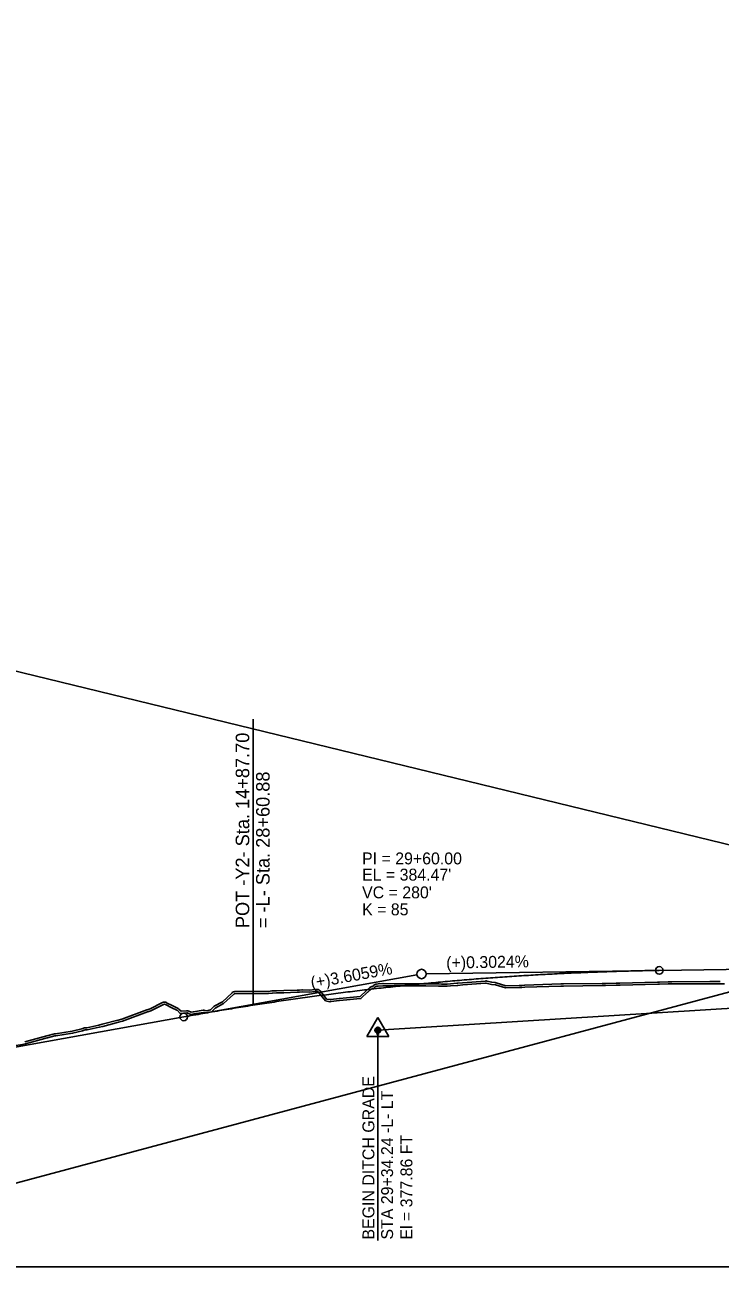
# Model space of a CAD drawing. Extents: x 1625686 to 1640492, y 1161393 to 1175642.
# Drawn here: x 1637638 to 1638048, y 1174911 to 1175642 of the extents above; entities that cross this region are included whole.
import ezdxf

# ---------------------------------------------------------------- set-up
doc = ezdxf.new("R2010")
doc.units = 0
for name, color, linetype in [('Exist Profile Cell', 7, 'Continuous'), ('Prop PFL Text', 7, 'Continuous'), ('Prop Vertical Profile Curve Label', 7, 'Continuous'), ('Prop Vertical Profile Ditch Grade Left', 7, 'Continuous'), ('Prop Vertical Profile Grade', 7, 'Continuous'), ('Prop Vertical Profile Grade Label', 7, 'Continuous'), ('Prop VPI Ditch Grade Left Label', 7, 'Continuous'), ('Prop VPI Label', 7, 'Continuous'), ('Scratch_Level_1', 7, 'Continuous'), ('Scratch_Level_3', 7, 'Continuous')]:
    doc.layers.add(name, color=color, linetype=linetype)

msp = doc.modelspace()

# ---------------------------------------------------------------- linework, layer by layer
at = {"layer": 'Exist Profile Cell'}
msp.add_line((1635911.78, 1174910.79), (1640378.1, 1174910.79), dxfattribs=at)
at = {"layer": 'Prop PFL Text'}
msp.add_line((1637772.66, 1175064.77), (1637772.66, 1175233.25), dxfattribs=at)
at = {"layer": 'Prop Vertical Profile Curve Label'}
for centre in [(1638011.78, 1175085.25), (1637731.78, 1175057.9)]:
    msp.add_circle(centre, 2.25, dxfattribs=at)
at = {"layer": 'Prop Vertical Profile Ditch Grade Left'}
msp.add_line((1637846.02, 1175050.09), (1638361.78, 1175082.04), dxfattribs=at)
at = {"layer": 'Prop Vertical Profile Grade'}
for p, q in [((1638011.78, 1175085.25), (1638636.78, 1175094.7)), ((1637591.78, 1175032.65), (1637731.78, 1175057.9))]:
    msp.add_line(p, q, dxfattribs=at)
msp.add_spline([(1637731.78, 1175057.9), (1637737.38, 1175058.9), (1637742.98, 1175059.88), (1637748.58, 1175060.84), (1637754.18, 1175061.79), (1637759.78, 1175062.71), (1637765.38, 1175063.62), (1637770.98, 1175064.51), (1637776.58, 1175065.38), (1637782.18, 1175066.23), (1637787.78, 1175067.07), (1637793.38, 1175067.88), (1637798.98, 1175068.68), (1637804.58, 1175069.46), (1637810.18, 1175070.22), (1637815.78, 1175070.96), (1637821.38, 1175071.68), (1637826.98, 1175072.39), (1637832.58, 1175073.07), (1637838.18, 1175073.74), (1637843.78, 1175074.39), (1637849.38, 1175075.02), (1637854.98, 1175075.63), (1637860.58, 1175076.22), (1637866.18, 1175076.8), (1637871.78, 1175077.36), (1637877.38, 1175077.89), (1637882.98, 1175078.41), (1637888.58, 1175078.91), (1637894.18, 1175079.4), (1637899.78, 1175079.86), (1637905.38, 1175080.31), (1637910.98, 1175080.73), (1637916.58, 1175081.14), (1637922.18, 1175081.53), (1637927.78, 1175081.9), (1637933.38, 1175082.26), (1637938.98, 1175082.59), (1637944.58, 1175082.91), (1637950.18, 1175083.2), (1637955.78, 1175083.48), (1637961.38, 1175083.74), (1637966.98, 1175083.98), (1637972.58, 1175084.21), (1637978.18, 1175084.41), (1637983.78, 1175084.6), (1637989.38, 1175084.77), (1637994.98, 1175084.92), (1638000.58, 1175085.05), (1638006.18, 1175085.16), (1638011.78, 1175085.25)], degree=3, dxfattribs=at)
at = {"layer": 'Prop VPI Ditch Grade Left Label'}
for p, q in [((1637846.02, 1175057.57), (1637839.57, 1175046.37)), ((1637846.02, 1175057.57), (1637852.52, 1175046.37)), ((1637846.02, 1175050.09), (1637846.02, 1174926.27)), ((1637839.57, 1175046.37), (1637852.52, 1175046.37))]:
    msp.add_line(p, q, dxfattribs=at)
for centre, radius in [((1637846.02, 1175050.09), 1.75), ((1637846.02, 1175050.09), 1.2), ((1637846.02, 1175050.09), 0.5), ((1637846.02, 1175047.79), 0.5)]:
    msp.add_circle(centre, radius, dxfattribs=at)
at = {"layer": 'Prop VPI Label'}
for p, q in [((1637731.78, 1175057.9), (1637869.08, 1175082.65)), ((1638011.78, 1175085.25), (1637874.53, 1175083.18))]:
    msp.add_line(p, q, dxfattribs=at)
msp.add_circle((1637871.78, 1175083.14), 2.75, dxfattribs=at)
at = {"layer": 'Scratch_Level_1'}
for p, q in [((1637783.91, 1175073.18), (1637786.36, 1175073.27)), ((1637783.95, 1175071.93), (1637786.4, 1175072.02)), ((1637811.05, 1175072.42), (1637813.26, 1175069.71)), ((1637812.02, 1175073.2), (1637814.23, 1175070.5)), ((1637839.3, 1175073.42), (1637841.41, 1175075.21)), ((1637840.11, 1175072.47), (1637842.22, 1175074.25)), ((1637843.02, 1175075.8), (1637843.69, 1175076.47)), ((1637895.97, 1175077.97), (1637909.45, 1175079.02)), ((1637896.07, 1175076.72), (1637909.55, 1175077.77)), ((1637932.63, 1175076.59), (1637953.79, 1175077.3)), ((1637932.67, 1175075.34), (1637953.84, 1175076.05)), ((1638019.27, 1175078.58), (1638041.48, 1175078.69)), ((1638019.27, 1175077.33), (1638041.49, 1175077.44)), ((1637737.46, 1175060.89), (1637743.18, 1175061.77)), ((1637737.65, 1175059.65), (1637743.37, 1175060.53)), ((1637638.17, 1175043.3), (1637651.09, 1175046.76)), ((1637638.49, 1175042.09), (1637651.41, 1175045.55)), ((1637651.14, 1175046.77), (1637655.61, 1175047.87)), ((1637651.44, 1175045.56), (1637655.91, 1175046.66)), ((1637655.72, 1175047.89), (1637656.05, 1175047.96)), ((1637655.96, 1175046.67), (1637656.3, 1175046.74))]:
    msp.add_line(p, q, dxfattribs=at)
for points in [[(1637749.73, 1175064.15), (1637754.49, 1175066.71), (1637760.18, 1175072.08)], [(1637761.88, 1175072.76), (1637781.57, 1175072.92), (1637783.71, 1175073.17)], [(1637786.37, 1175073.27), (1637790.73, 1175073.4), (1637798.48, 1175073.62), (1637799.91, 1175073.71), (1637801.34, 1175073.81)], [(1637786.41, 1175072.02), (1637790.76, 1175072.15), (1637798.54, 1175072.37), (1637799.99, 1175072.47), (1637801.42, 1175072.56)], [(1637801.54, 1175072.56), (1637805.76, 1175072.4), (1637809.2, 1175072.78), (1637809.94, 1175072.87)], [(1637801.59, 1175073.81), (1637805.72, 1175073.65), (1637809.06, 1175074.03), (1637809.8, 1175074.11)], [(1637833.66, 1175069.7), (1637835.56, 1175069.86), (1637839.19, 1175073.32)], [(1637833.76, 1175068.46), (1637836.1, 1175068.65), (1637836.29, 1175068.82), (1637840.05, 1175072.42)], [(1637843.21, 1175074.54), (1637843.49, 1175074.5), (1637844.57, 1175075.59)], [(1637845.29, 1175077.21), (1637846.25, 1175077.27), (1637849, 1175077.46)], [(1637845.38, 1175075.96), (1637846.34, 1175076.03), (1637849.09, 1175076.21)], [(1637849.18, 1175076.22), (1637855.7, 1175076.18), (1637864.97, 1175076.14), (1637870.88, 1175076.11), (1637872.93, 1175076.14)], [(1637849.19, 1175077.47), (1637855.7, 1175077.43), (1637864.97, 1175077.39), (1637870.88, 1175077.36), (1637872.9, 1175077.39)], [(1637872.96, 1175076.14), (1637874.24, 1175076.13), (1637881.77, 1175076.06)], [(1637872.97, 1175077.39), (1637874.26, 1175077.38), (1637881.78, 1175077.31)], [(1637881.82, 1175076.06), (1637883.53, 1175075.97), (1637886.92, 1175075.97), (1637888.87, 1175076.11), (1637892.68, 1175076.4), (1637893.25, 1175076.44), (1637896.04, 1175076.72)], [(1637881.88, 1175077.31), (1637883.56, 1175077.22), (1637886.87, 1175077.22), (1637888.78, 1175077.36), (1637892.58, 1175077.65), (1637893.14, 1175077.69), (1637895.92, 1175077.97)], [(1637909.94, 1175077.74), (1637912.9, 1175077.02), (1637915.12, 1175076.81)], [(1637910.24, 1175078.96), (1637913.11, 1175078.26), (1637915.23, 1175078.05)], [(1637915.36, 1175076.76), (1637921.32, 1175074.96), (1637929.4, 1175075.14), (1637930.95, 1175075.18), (1637932.6, 1175075.34)], [(1637915.72, 1175077.96), (1637921.49, 1175076.21), (1637929.37, 1175076.39), (1637930.88, 1175076.43), (1637932.48, 1175076.58)], [(1637953.9, 1175076.05), (1637954.65, 1175076.03), (1637955.45, 1175076.04), (1637978.16, 1175076.36)], [(1637953.93, 1175077.3), (1637954.66, 1175077.28), (1637955.44, 1175077.29), (1637978.14, 1175077.61)], [(1637978.2, 1175076.36), (1637979.1, 1175076.35), (1637980.08, 1175076.38)], [(1637978.23, 1175077.61), (1637979.09, 1175077.6), (1637980.03, 1175077.63)], [(1637980.09, 1175077.63), (1637986.33, 1175077.72), (1637987.41, 1175077.76)], [(1637980.11, 1175076.38), (1637986.36, 1175076.47), (1637987.45, 1175076.51)], [(1637987.51, 1175076.51), (1637988.68, 1175076.49), (1638010.87, 1175077.16)], [(1637987.54, 1175077.76), (1637988.67, 1175077.74), (1638010.84, 1175078.41)], [(1638010.9, 1175078.41), (1638011.87, 1175078.42), (1638017.05, 1175078.57)], [(1638010.91, 1175077.16), (1638011.89, 1175077.17), (1638017.09, 1175077.33)], [(1638017.19, 1175077.32), (1638018.16, 1175077.28), (1638019.22, 1175077.33)], [(1638017.26, 1175078.57), (1638018.16, 1175078.53), (1638019.16, 1175078.58)], [(1638041.53, 1175077.44), (1638042.66, 1175077.41), (1638047.5, 1175077.43)], [(1638041.56, 1175078.69), (1638042.67, 1175078.66), (1638047.5, 1175078.68)], [(1638047.58, 1175077.43), (1638048.8, 1175077.36), (1638050.17, 1175077.34)], [(1637710.23, 1175062.14), (1637711.93, 1175062.59), (1637719.22, 1175066.28)], [(1637710.55, 1175060.93), (1637712.38, 1175061.41), (1637719.78, 1175065.16)], [(1637720.93, 1175065.15), (1637724.69, 1175063.18), (1637727.62, 1175061.87)], [(1637721.51, 1175066.26), (1637725.24, 1175064.31), (1637728.14, 1175063.01)], [(1637750.32, 1175063.05), (1637755.23, 1175065.68), (1637761.04, 1175071.17)], [(1637761.89, 1175071.51), (1637781.65, 1175071.67), (1637783.85, 1175071.92)], [(1637813.26, 1175069.71), (1637815.24, 1175067.26), (1637817.83, 1175066.78), (1637818.46, 1175066.86), (1637823.5, 1175067.51)], [(1637814.23, 1175070.49), (1637815.92, 1175068.4), (1637817.87, 1175068.04), (1637818.3, 1175068.1), (1637823.34, 1175068.75)], [(1637823.44, 1175068.76), (1637827.65, 1175069.15), (1637833.63, 1175069.7)], [(1637823.55, 1175067.52), (1637827.77, 1175067.91), (1637833.74, 1175068.46)], [(1637693.08, 1175056.05), (1637695.35, 1175056.59), (1637709.98, 1175062.06)], [(1637693.37, 1175054.83), (1637695.72, 1175055.39), (1637710.42, 1175060.89)], [(1637727.99, 1175061.62), (1637729.74, 1175059.91), (1637733.55, 1175060.27)], [(1637728.86, 1175062.51), (1637730.2, 1175061.21), (1637733.43, 1175061.52)], [(1637734.23, 1175060.15), (1637735.92, 1175059.31), (1637737.6, 1175059.64)], [(1637734.78, 1175061.27), (1637736.1, 1175060.62), (1637737.35, 1175060.87)], [(1637743.82, 1175060.52), (1637745.32, 1175060.2), (1637748.19, 1175060.92), (1637750.02, 1175062.82)], [(1637744.08, 1175061.74), (1637745.3, 1175061.48), (1637747.54, 1175062.05), (1637749.11, 1175063.68)], [(1637656.16, 1175047.98), (1637666.06, 1175049.52), (1637671.72, 1175050.94), (1637673.35, 1175051.38)], [(1637656.35, 1175046.75), (1637666.3, 1175048.29), (1637672.04, 1175049.73), (1637673.68, 1175050.18)], [(1637674.06, 1175050.22), (1637674.39, 1175050.2), (1637674.78, 1175050.23), (1637681.99, 1175051.8), (1637684.01, 1175052.32), (1637693.34, 1175054.82)], [(1637674.12, 1175051.47), (1637674.38, 1175051.46), (1637674.61, 1175051.47), (1637681.71, 1175053.01), (1637683.69, 1175053.53), (1637693.01, 1175056.03)], [(1637615.09, 1175038.35), (1637636.81, 1175041.69), (1637637.61, 1175041.85), (1637638.48, 1175042.09)]]:
    msp.add_lwpolyline(points, dxfattribs=at)
for centre, radius, start, end in [((1637761.9, 1175070.26), 2.5, 90.45637, 133.36574), ((1637784, 1175070.68), 2.5, 92.0965, 96.67071), ((1637786.45, 1175070.77), 2.5, 91.66065, 92.0965), ((1637786.45, 1175070.77), 1.25, 91.66065, 92.0965), ((1637801.5, 1175071.31), 2.5, 87.79624, 93.66933), ((1637801.5, 1175071.31), 1.25, 87.79624, 93.66933), ((1637810.08, 1175071.63), 2.5, 39.17888, 96.41969), ((1637810.08, 1175071.63), 1.25, 39.17888, 96.41969), ((1637840.92, 1175071.52), 2.5, 130.21039, 133.69679), ((1637840.92, 1175071.52), 1.25, 130.21039, 133.69679), ((1637843.03, 1175073.3), 2.5, 90.24247, 130.21039), ((1637843.03, 1175073.3), 1.25, 81.82241, 130.21039), ((1637845.46, 1175074.71), 2.5, 93.90401, 135.22839), ((1637845.46, 1175074.71), 1.25, 93.90401, 135.22839), ((1637849.17, 1175074.97), 2.5, 89.70817, 93.90986), ((1637849.17, 1175074.97), 1.25, 89.70817, 93.90986), ((1637872.95, 1175074.89), 2.5, 89.42738, 90.97147), ((1637872.95, 1175074.89), 1.25, 89.42738, 90.97147), ((1637881.76, 1175074.81), 1.25, 87.22873, 89.44288), ((1637881.76, 1175074.81), 2.5, 87.22873, 89.44288), ((1637896.17, 1175075.48), 2.5, 94.45073, 95.67591), ((1637896.17, 1175075.48), 1.25, 94.45073, 95.67591), ((1637909.64, 1175076.53), 2.5, 76.3014, 94.45073), ((1637909.64, 1175076.53), 1.25, 76.3014, 94.45073), ((1637915, 1175075.56), 1.25, 73.17049, 84.52842), ((1637915, 1175075.56), 2.5, 73.17049, 84.52842), ((1637932.71, 1175074.09), 2.5, 91.91962, 95.25594), ((1637932.71, 1175074.09), 1.25, 91.91962, 95.25594), ((1637953.88, 1175074.8), 2.5, 88.74727, 91.91962), ((1637953.88, 1175074.8), 1.25, 88.74727, 91.91962), ((1637978.18, 1175075.11), 2.5, 88.81658, 90.82933), ((1637978.18, 1175075.11), 1.25, 88.81658, 90.82933), ((1637980.13, 1175075.13), 2.5, 90.83069, 92.10222), ((1637980.13, 1175075.13), 1.25, 90.83069, 92.10222), ((1637987.49, 1175075.26), 2.5, 88.9436, 91.81796), ((1637987.49, 1175075.26), 1.25, 88.9436, 91.81796), ((1638010.91, 1175075.91), 2.5, 90.21445, 91.74121), ((1638010.91, 1175075.91), 1.25, 90.21445, 91.74121), ((1638017.13, 1175076.08), 2.5, 87.08191, 91.75962), ((1638017.13, 1175076.08), 1.25, 87.08191, 91.75962), ((1638019.28, 1175076.08), 2.5, 90.27858, 92.76798), ((1638019.28, 1175076.08), 1.25, 90.27858, 92.76798), ((1638041.5, 1175076.19), 2.5, 88.61995, 90.27858), ((1638041.5, 1175076.19), 1.25, 88.61995, 90.27858), ((1638047.51, 1175076.18), 2.5, 86.55045, 90.27052), ((1638047.51, 1175076.18), 1.25, 86.55045, 90.27052), ((1637720.35, 1175064.05), 2.5, 62.34021, 116.87493), ((1637720.35, 1175064.05), 1.25, 62.34021, 116.87493), ((1637761.9, 1175070.26), 1.25, 90.45637, 133.36574), ((1637784, 1175070.68), 1.25, 92.0965, 96.67071), ((1637812.29, 1175068.92), 1.25, 38.91411, 39.17888), ((1637812.29, 1175068.92), 2.5, 38.91411, 39.17888), ((1637823.67, 1175066.27), 2.5, 95.23946, 97.43906), ((1637823.67, 1175066.27), 1.25, 95.23946, 97.43906), ((1637833.86, 1175067.21), 2.5, 94.60113, 95.25038), ((1637833.86, 1175067.21), 1.25, 94.60113, 95.25038), ((1637710.86, 1175059.72), 2.5, 104.61158, 110.51515), ((1637710.86, 1175059.72), 1.25, 104.61158, 110.51515), ((1637727.11, 1175060.73), 1.25, 45.66731, 65.83967), ((1637727.11, 1175060.73), 2.5, 45.66731, 65.83967), ((1637733.67, 1175059.03), 2.5, 63.69776, 95.52653), ((1637733.67, 1175059.03), 1.25, 63.69776, 95.52653), ((1637737.84, 1175058.42), 2.5, 98.73246, 101.23229), ((1637737.84, 1175058.42), 1.25, 98.73246, 101.23229), ((1637743.56, 1175059.3), 2.5, 78.00805, 98.73246), ((1637743.56, 1175059.3), 1.25, 78.00805, 98.73246), ((1637750.92, 1175061.95), 2.5, 118.23279, 136.10317), ((1637750.92, 1175061.95), 1.25, 118.23279, 136.10317), ((1637674.01, 1175048.97), 2.5, 87.48273, 105.11958), ((1637674.01, 1175048.97), 1.25, 87.48273, 105.11958), ((1637693.66, 1175053.62), 2.5, 103.39269, 105.02668), ((1637693.66, 1175053.62), 1.25, 103.39269, 105.02668), ((1637651.73, 1175044.34), 2.5, 103.8307, 104.97241), ((1637651.73, 1175044.34), 1.25, 103.8307, 104.97241), ((1637656.21, 1175045.44), 2.5, 101.45585, 103.8307), ((1637656.21, 1175045.44), 1.25, 101.45585, 103.8307), ((1637656.55, 1175045.51), 2.5, 98.83757, 101.45585), ((1637656.55, 1175045.51), 1.25, 98.83757, 101.45585), ((1637638.81, 1175040.89), 1.25, 104.97241, 105.66396)]:
    msp.add_arc(centre, radius, start, end, dxfattribs=at)
at = {"layer": 'Scratch_Level_3'}
for p, q in [((1636069.38, 1175641.97), (1640127.74, 1174654.21)), ((1636080.34, 1174544.46), (1640138.71, 1175631))]:
    msp.add_line(p, q, dxfattribs=at)
msp.add_lwpolyline([(1635911.78, 1174910.79), (1640049.19, 1174910.79), (1640049.19, 1175362.47)], dxfattribs=at)

# ---------------------------------------------------------------- texts
at = {"layer": 'Prop PFL Text'}
for s, p in [('POT -Y2- Sta. 14+87.70', (1637770.34, 1175110.16)), ('= -L- Sta. 28+60.88', (1637782.34, 1175110.16))]:
    msp.add_text(s, height=8, rotation=90, dxfattribs=at).set_placement(p)
at = {"layer": 'Prop Vertical Profile Curve Label'}
for s, p in [("VC = 280'", (1637836.78, 1175127.69)), ('K = 85', (1637836.78, 1175117.69))]:
    msp.add_text(s, height=7, dxfattribs=at).set_placement(p)
at = {"layer": 'Prop Vertical Profile Grade Label'}
for s, rotation, p in [('(+)0.3024%', 0.86627, (1637886.39, 1175086.36)), ('(+)3.6059%', 10.2203, (1637807.15, 1175074.53))]:
    msp.add_text(s, height=7, rotation=rotation, dxfattribs=at).set_placement(p)
at = {"layer": 'Prop VPI Ditch Grade Left Label'}
for s, p in [('BEGIN DITCH GRADE', (1637844.02, 1174926.79)), ('STA 29+34.24 -L- LT', (1637855.02, 1174926.79)), ('El = 377.86 FT', (1637866.4, 1174926.79))]:
    msp.add_text(s, height=7, rotation=90, dxfattribs=at).set_placement(p)
at = {"layer": 'Prop VPI Label'}
for s, p in [('PI = 29+60.00', (1637836.78, 1175147.69)), ("EL = 384.47'", (1637836.78, 1175138.14))]:
    msp.add_text(s, height=7, dxfattribs=at).set_placement(p)

doc.saveas('drawing.dxf')
